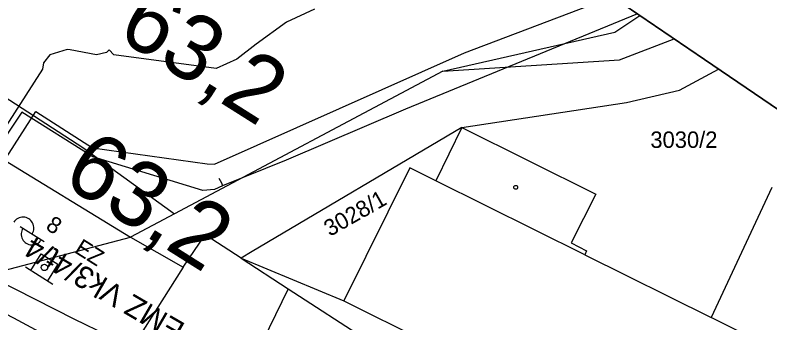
# Model space of a CAD drawing. Extents: x -621145 to -620110, y -1122807 to -1121971.
# Drawn here: x -620456.4 to -620387.4, y -1122571.8 to -1122543.7 of the extents above; entities that cross this region are included whole.
import ezdxf

# ---------------------------------------------------------------- set-up
doc = ezdxf.new("R2010")
doc.units = 0
for name, color, linetype in [('060601_EOV', 7, 'Continuous'), ('060604_ROZVODY_SEE', 7, 'Continuous'), ('itself', 7, 'Continuous'), ('RÁMY', 7, 'Continuous'), ('VAS stoka', 7, 'Continuous'), ('VAS vodovod', 7, 'Continuous'), ('Vrstva 1', 7, 'Continuous'), ('Vrstva 25', 7, 'Continuous'), ('Vrstva 3', 7, 'Continuous'), ('Vrstva 53', 7, 'Continuous'), ('Vrstva 55', 7, 'Continuous'), ('Vrstva 56', 7, 'Continuous'), ('Vrstva 57', 7, 'Continuous'), ('Vrstva 62', 7, 'Continuous'), ('Vrstva 7', 7, 'Continuous')]:
    doc.layers.add(name, color=color, linetype=linetype)

msp = doc.modelspace()

# ---------------------------------------------------------------- linework, layer by layer
at = {"layer": '060601_EOV'}
msp.add_lwpolyline([(-620343.182, -1122658.459), (-620368.499, -1122642.897), (-620411.557, -1122614.916), (-620424.156, -1122607.087), (-620443.525, -1122595.005), (-620456.111, -1122587.123), (-620447.823, -1122572.959), (-620450.948, -1122571.455), (-620470.592, -1122561.479), (-620499.61, -1122545.574), (-620522.038, -1122531.471), (-620538.89, -1122521.208), (-620599.215, -1122483.216), (-620683.524, -1122429.444)], dxfattribs=at)
at = {"layer": '060604_ROZVODY_SEE'}
msp.add_lwpolyline([(-620443.525, -1122595.005), (-620456.111, -1122587.123), (-620447.823, -1122572.959), (-620450.948, -1122571.455), (-620470.592, -1122561.479), (-620499.61, -1122545.574), (-620522.038, -1122531.471), (-620538.89, -1122521.208), (-620599.215, -1122483.216), (-620683.524, -1122429.444), (-620756.33, -1122383.523), (-620765.796, -1122398.395)], dxfattribs=at)
at = {"layer": 'itself'}
msp.add_lwpolyline([(-620428.996, -1122543.132), (-620431.546, -1122544.332), (-620434.336, -1122546.352), (-620436.096, -1122547.702), (-620437.986, -1122548.562), (-620447.326, -1122547.322), (-620447.756, -1122546.852), (-620448.006, -1122547.092), (-620448.926, -1122547.312), (-620451.316, -1122546.862), (-620451.596, -1122546.822), (-620453.176, -1122547.322), (-620453.756, -1122548.032), (-620453.846, -1122548.622), (-620474.586, -1122580.832)], dxfattribs=at)
at = {"layer": 'RÁMY'}
for points in [[(-621061.558, -1122093.918), (-620192.937, -1122683.831), (-620276.367, -1122806.679), (-621144.989, -1122216.766)], [(-620887.834, -1122211.901), (-620192.937, -1122683.831), (-620276.367, -1122806.679), (-620971.264, -1122334.748)], [(-620370.093, -1122384.009), (-620283.231, -1122443.001), (-620366.661, -1122565.848), (-620453.523, -1122506.857)]]:
    msp.add_lwpolyline(points, close=True, dxfattribs=at)
at = {"layer": 'VAS stoka'}
for p, q in [((-620415.28, -1122547.13), (-620401.768, -1122542.006)), ((-620438.13, -1122557.28), (-620415.28, -1122547.13))]:
    msp.add_line(p, q, dxfattribs=at)
msp.add_lwpolyline([(-620544.25, -1122585.029), (-620545.68, -1122585.41), (-620545.7, -1122585.34), (-620544.74, -1122585.09), (-620529.09, -1122581.01), (-620528.27, -1122580.72), (-620501.26, -1122592.08), (-620484.32, -1122584.76), (-620478.68, -1122582.19), (-620475.52, -1122584.33), (-620473.62, -1122582.33), (-620454.46, -1122552.49), (-620449.28, -1122555.81), (-620438.79, -1122557.25), (-620438.13, -1122557.28)], dxfattribs=at)
at = {"layer": 'VAS vodovod'}
for points in [[(-620399.455, -1122543.577), (-620420.68, -1122552.27), (-620431.57, -1122556.92), (-620437.4, -1122559.27), (-620438.12, -1122559.6), (-620439.2, -1122559.69), (-620449.24, -1122556.62), (-620455.75, -1122552.55), (-620475.62, -1122582.28), (-620474.72, -1122582.95), (-620476.62, -1122585.56), (-620476.869, -1122585.61)], [(-620437.72, -1122558.57), (-620437.49, -1122558.99), (-620437.4, -1122559.27)]]:
    msp.add_lwpolyline(points, dxfattribs=at)
at = {"layer": 'Vrstva 1'}
msp.add_lwpolyline([(-620500.939, -1122547.694), (-620489.166, -1122554.597), (-620480.63, -1122559.224), (-620478.824, -1122560.172), (-620471.759, -1122563.69), (-620469.127, -1122564.967), (-620462.69, -1122568.112), (-620456.494, -1122571.322), (-620452.14, -1122573.653), (-620443.341, -1122578.74), (-620440.571, -1122580.341), (-620433.381, -1122584.662), (-620423.009, -1122591.081), (-620412.157, -1122597.915), (-620389.938, -1122611.924), (-620377.691, -1122619.641), (-620371.626, -1122623.45), (-620362.665, -1122629.103), (-620357.095, -1122632.621), (-620348.688, -1122637.935), (-620341.5, -1122642.47)], dxfattribs=at)
at = {"layer": 'Vrstva 25'}
msp.add_line((-620455.899, -1122562.969), (-620453.699, -1122564.354), dxfattribs=at)
for centre, start, end in [((-620455.645, -1122563.129), 327.79168, 147.79168), ((-620454.805, -1122563.672), 147.0891, 328.49425)]:
    msp.add_arc(centre, 1, start, end, dxfattribs=at)
at = {"layer": 'Vrstva 3'}
msp.add_line((-620455.411, -1122566.677), (-620452.909, -1122568.253), dxfattribs=at)
msp.add_lwpolyline([(-620454.911, -1122566.992), (-620453.965, -1122565.491), (-620452.464, -1122566.436), (-620453.409, -1122567.938)], dxfattribs=at)
msp.add_circle((-620453.685, -1122566.715), 0.296, dxfattribs=at)
at = {"layer": 'Vrstva 53'}
for p, q in [((-620552.09, -1122499.2), (-620445.8, -1122563.95)), ((-620440.98, -1122566.69), (-620438.97, -1122563.76)), ((-620435.69, -1122565.88), (-620438.97, -1122563.76)), ((-620445.8, -1122563.95), (-620440.98, -1122566.69)), ((-620435.69, -1122565.88), (-620431.39, -1122568.66)), ((-620440.98, -1122566.69), (-620447.48, -1122576.88)), ((-620431.39, -1122568.66), (-620434.26, -1122574.5))]:
    msp.add_line(p, q, dxfattribs=at)
at = {"layer": 'Vrstva 55'}
for p, q in [((-620552.09, -1122499.2), (-620445.8, -1122563.95)), ((-620475.79, -1122539.24), (-620450.17, -1122555.76)), ((-620401.53, -1122545.24), (-620399.251, -1122543.716)), ((-620417.25, -1122548.82), (-620401.53, -1122545.24)), ((-620417.25, -1122548.82), (-620441.78, -1122561.82)), ((-620415.52, -1122553.94), (-620434.68, -1122565.28)), ((-620415.52, -1122553.94), (-620417.91, -1122558.83)), ((-620415.52, -1122553.94), (-620403.26, -1122560.03)), ((-620450.17, -1122555.76), (-620441.78, -1122561.82)), ((-620420.27, -1122557.63), (-620426.32, -1122569.77)), ((-620417.91, -1122558.83), (-620420.27, -1122557.63)), ((-620387.17, -1122559.43), (-620392.72, -1122571.3)), ((-620403.26, -1122560.03), (-620405.52, -1122564.49)), ((-620441.78, -1122561.82), (-620445.8, -1122563.95)), ((-620440.98, -1122566.69), (-620438.97, -1122563.76)), ((-620435.69, -1122565.88), (-620438.97, -1122563.76)), ((-620445.8, -1122563.95), (-620440.98, -1122566.69)), ((-620405.52, -1122564.49), (-620404.12, -1122565.22)), ((-620434.68, -1122565.28), (-620435.69, -1122565.88)), ((-620435.69, -1122565.88), (-620426.32, -1122569.77)), ((-620435.69, -1122565.88), (-620431.39, -1122568.66)), ((-620404.12, -1122565.22), (-620404.28, -1122565.56)), ((-620404.28, -1122565.56), (-620392.72, -1122571.3)), ((-620440.98, -1122566.69), (-620447.48, -1122576.88)), ((-620431.39, -1122568.66), (-620434.26, -1122574.5)), ((-620431.39, -1122568.66), (-620411.27, -1122581.65)), ((-620426.32, -1122569.77), (-620402.04, -1122581.77)), ((-620378.57, -1122578.31), (-620392.72, -1122571.3))]:
    msp.add_line(p, q, dxfattribs=at)
at = {"layer": 'Vrstva 56'}
for p, q in [((-620401.09, -1122547.76), (-620396.115, -1122545.845)), ((-620417.25, -1122548.82), (-620401.09, -1122547.76)), ((-620395.61, -1122550.55), (-620392.041, -1122548.612)), ((-620400.46, -1122551.66), (-620395.61, -1122550.55)), ((-620415.52, -1122553.94), (-620400.46, -1122551.66)), ((-620404.28, -1122565.56), (-620417.91, -1122558.83)), ((-620485.21, -1122574.33), (-620445.8, -1122563.95))]:
    msp.add_line(p, q, dxfattribs=at)
at = {"layer": 'Vrstva 57'}
msp.add_circle((-620410.59, -1122559.41), 0.175, dxfattribs=at)
at = {"layer": 'Vrstva 62'}
msp.add_line((-620456.173, -1122570.683), (-620456.173, -1122570.683), dxfattribs=at)

# ---------------------------------------------------------------- texts
at = {"layer": 'Vrstva 25'}
msp.add_text('8', height=1.5, rotation=327.79168, dxfattribs=at).set_placement((-620453.651, -1122563.187))
at = {"layer": 'Vrstva 3'}
for s, height, rotation, p in [('EMZ Vk3/4t/4', 2, 149.82357, (-620440.693, -1122571.919)), ('EZ', 1.5, 327.80189, (-620451.026, -1122565.303))]:
    msp.add_text(s, height=height, rotation=rotation, dxfattribs=at).set_placement(p)
at = {"layer": 'Vrstva 57'}
msp.add_text('3030/2', height=1.5, dxfattribs=at).set_placement((-620398.284, -1122555.81))
msp.add_text('3028/1', height=1.5, rotation=29.7, dxfattribs=at).set_placement((-620427.583, -1122563.942))
at = {"layer": 'Vrstva 7'}
for rotation, p in [(327.79168, (-620447.259, -1122545.598)), (327.80191, (-620452.255, -1122558.955))]:
    msp.add_text('63,2', height=6, rotation=rotation, dxfattribs=at).set_placement(p)

doc.saveas('drawing.dxf')
